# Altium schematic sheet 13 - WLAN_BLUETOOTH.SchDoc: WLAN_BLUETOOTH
size A3; Date: 21-DEC-2018; Author: CR; CompanyName: Octavo Systems LLC; Address2: Austin,TX; Address3: USA; DocumentNumber: DK2 RefDes; Revision: C-01; SheetNumber: 13; SheetTotal: 14
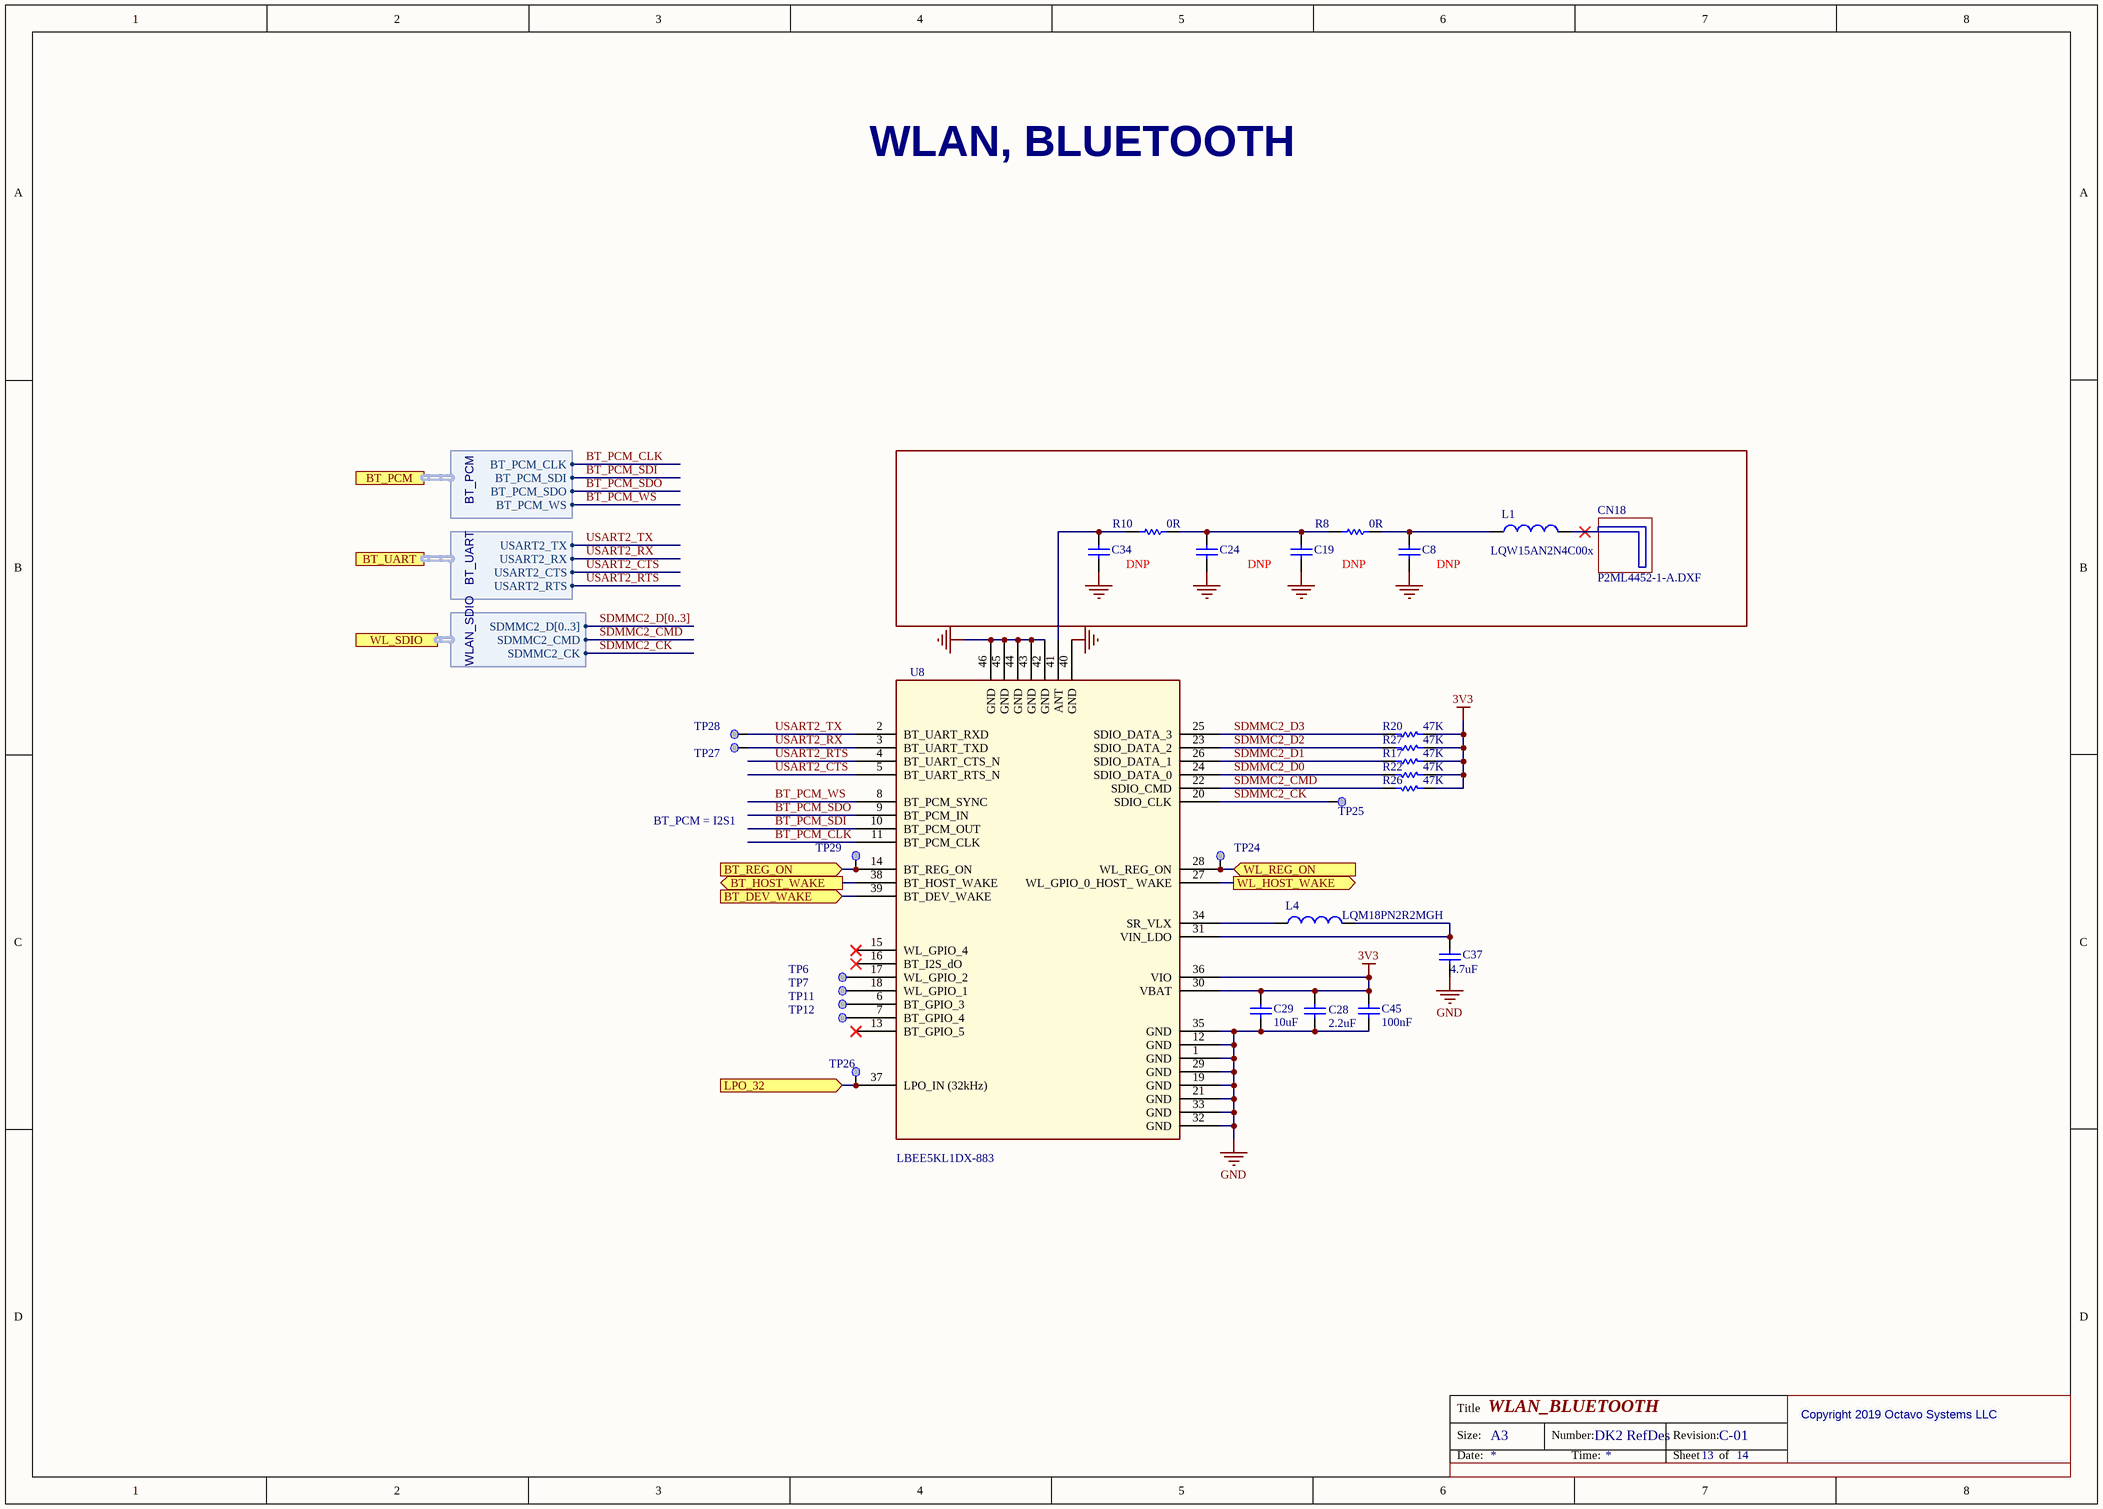
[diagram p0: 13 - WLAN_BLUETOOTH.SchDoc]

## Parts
C8  Capacitor  [C0402]  (value not drawn)  (no BOM)
C19  Capacitor  [C0402]  (value not drawn)  (no BOM)
C24  Capacitor  [C0402]  (value not drawn)  (no BOM)
C28  value 2.2uF  [C0603]  (hidden comment: Capacitor)
C29  value 10uF  [C0603]  (hidden comment: Capacitor)
C34  Capacitor  [C0402]  (value not drawn)  (no BOM)
C37  value 4.7uF  [C0402]
C45  value 100nF  [C0402]
CN18  value P2ML4452-1-A.DXF  [ANT_MURATA_TYPE-1-DX_P2ML4452-1-A_DXF]  (hidden comment: antenna_Wifi_BLE_Murata)  (graphical)
L1  value LQW15AN2N4C00x  [IND_0402_MURATA_LQW15AN2N4C00X]  (hidden comment: Inductor)
L4  value LQM18PN2R2MGH  [L0603]  (hidden comment: Inductor)
R8  value 0R  [R0402]  (hidden comment: Resistor)
R10  value 0R  [R0402]  (hidden comment: Resistor)
R17  value 47K  [R0402]  (hidden comment: Resistor)
R20  value 47K  [R0402]  (hidden comment: Resistor)
R22  value 47K  [R0402]  (hidden comment: Resistor)
R26  value 47K  [R0402]  (hidden comment: Resistor)
R27  value 47K  [R0402]  (hidden comment: Resistor)
TP6  Test Point  [TP_SMD_1MM]  (value not drawn)  (no BOM)
TP7  Test Point  [TP_SMD_1MM]  (value not drawn)  (no BOM)
TP11  Test Point  [TP_SMD_1MM]  (value not drawn)  (no BOM)
TP12  Test Point  [TP_SMD_1MM]  (value not drawn)  (no BOM)
TP24  Test Point  [TP_SMD_0-6MM]  (value not drawn)  (no BOM)
TP25  Test Point  [TP_SMD_0-6MM]  (value not drawn)  (no BOM)
TP26  Test Point  [TP_SMD_0-6MM]  (value not drawn)  (no BOM)
TP27  Test Point  [TP_SMD_0-6MM]  (value not drawn)  (no BOM)
TP28  Test Point  [TP_SMD_0-6MM]  (value not drawn)  (no BOM)
TP29  Test Point  [TP_SMD_0-6MM]  (value not drawn)  (no BOM)
U8  LBEE5KL1DX-883  [MOD_WLAN-BT_MURATA_LBEE5KL1DX-883]

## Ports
BT_DEV_WAKE (in), BT_HOST_WAKE (out), BT_PCM (harness BT_PCM), BT_REG_ON (in), BT_UART (harness BT_UART), LPO_32 (in), WL_HOST_WAKE (out), WL_REG_ON (in), WL_SDIO (harness WLAN_SDIO)

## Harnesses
BT_PCM: BT_PCM_CLK, BT_PCM_SDI, BT_PCM_SDO, BT_PCM_WS
BT_UART: USART2_TX, USART2_RX, USART2_CTS, USART2_RTS
WLAN_SDIO: SDMMC2_D[0..3], SDMMC2_CMD, SDMMC2_CK

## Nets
3V3: C28.2 C29.2 C45.2 R17.1 R20.1 R22.1 R26.1 R27.1 U8.30(VBAT) U8.36(VIO)
GND: C8.1 C19.1 C24.1 C28.1 C29.1 C34.1 C37.1 C45.1 U8.1(GND) U8.12(GND) U8.19(GND) U8.21(GND) U8.29(GND) U8.32(GND) U8.33(GND) U8.35(GND) U8.40(GND) U8.42(GND) U8.43(GND) U8.44(GND) U8.45(GND) U8.46(GND)
BT_DEV_WAKE: U8.39(BT_DEV_WAKE) ; port BT_DEV_WAKE
BT_HOST_WAKE: U8.38(BT_HOST_WAKE) ; port BT_HOST_WAKE
BT_PCM_CLK: U8.11(BT_PCM_CLK) ; port BT_PCM.BT_PCM_CLK
BT_PCM_SDI: U8.10(BT_PCM_OUT) ; port BT_PCM.BT_PCM_SDI
BT_PCM_SDO: U8.9(BT_PCM_IN) ; port BT_PCM.BT_PCM_SDO
BT_PCM_WS: U8.8(BT_PCM_SYNC) ; port BT_PCM.BT_PCM_WS
BT_REG_ON: TP29.1 U8.14(BT_REG_ON) ; port BT_REG_ON
LPO_32: TP26.1 U8.37(LPO_IN_(32kHz)) ; port LPO_32
SDMMC2_CK: TP25.1 U8.20(SDIO_CLK) ; port WL_SDIO.SDMMC2_CK
SDMMC2_CMD: R26.2 U8.22(SDIO_CMD) ; port WL_SDIO.SDMMC2_CMD
SDMMC2_D0: R22.2 U8.24(SDIO_DATA_0)
SDMMC2_D1: R17.2 U8.26(SDIO_DATA_1)
SDMMC2_D2: R27.2 U8.23(SDIO_DATA_2)
SDMMC2_D3: R20.2 U8.25(SDIO_DATA_3)
USART2_CTS: U8.5(BT_UART_RTS_N) ; port BT_UART.USART2_CTS
USART2_RTS: U8.4(BT_UART_CTS_N) ; port BT_UART.USART2_RTS
USART2_RX: TP27.1 U8.3(BT_UART_TXD) ; port BT_UART.USART2_RX
USART2_TX: TP28.1 U8.2(BT_UART_RXD) ; port BT_UART.USART2_TX
WL_HOST_WAKE: U8.27(WL_GPIO_0_HOST__WAKE) ; port WL_HOST_WAKE
WL_REG_ON: TP24.1 U8.28(WL_REG_ON) ; port WL_REG_ON
NetC8_2: C8.2 L1.1 R8.1
NetC19_2: C19.2 C24.2 R8.2 R10.1
NetC34_2: C34.2 R10.2 U8.41(ANT)
NetC37_2: C37.2 L4.2 U8.31(VIN_LDO)
NetL4_1: L4.1 U8.34(SR_VLX)
NetTP6_1: TP6.1 U8.17(WL_GPIO_2)
NetTP7_1: TP7.1 U8.18(WL_GPIO_1)
NetTP11_1: TP11.1 U8.6(BT_GPIO_3)
NetTP12_1: TP12.1 U8.7(BT_GPIO_4)

Not connected (* = marked no-connect by the designer): L1 2*; U8 13(BT_GPIO_5)* 15(WL_GPIO_4)* 16(BT_I2S_dO)*

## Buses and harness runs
bus SDMMC2_D[0..3]

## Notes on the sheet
- WLAN, BLUETOOTH
- DNP
- (near C8) DNP
- BT_PCM = I2S1
- Copyright 2019 Octavo Systems LLC

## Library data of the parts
C8 C19 C24 C34 = MCD-00200: Capacitor, MLCC, 12pF, 50V, NPO, 5%, 0402, T=0,5mm; Manufacturer_Part_Number: CC0402JRNPO9BN120; Manufacturer: YAGEO; Provided_By: Subcon
C28 = MCD-00012: Capacitor, MLCC, 2.2uF, 10V, X5R, 10%, 0603, T=0,8mm; Manufacturer_Part_Number: CC0603KRX5R6BB225; Manufacturer: YAGEO; Alternate_Manufacturer_Part_Number: C0603C225K8PACTU; Alternate_Manufacturer: KEMET; Provided_By: Subcon; Initial_Board_Reference: MB1274
C29 = MCD-00099: Capacitor, MLCC, 10uF, 10V, X5R, 10%, 0603, T=0,8mm; Manufacturer_Part_Number: GRM188R61A106KE69D; Manufacturer: MURATA; ECCN_US: EAR99; ECCN_EU: NEC; Provided_By: Subcon; Initial_Board_Reference: MB1262
C37 = MCD-01356: Capacitor, MLCC, 4.7uF, 6V3, X5R, 20%, 0402, T=0,5mm; Manufacturer_Part_Number: GRM155R60J475ME47; Manufacturer: MURATA; Provided_By: SUBCO; Initial_Board_Reference: MB1372; Item Type: Item; Path: ws/MCD_ApplicationBoards/Lists/MCDPARTSdatabase
C45 = MCD-00006: Capacitor,100nF,16V,X7R,10%,0402; Manufacturer_Part_Number: CC0402KRX7R7BB104; Manufacturer: YAGEO; Provided_By: Subcon; Initial_Board_Reference: MB1274
CN18 = MCD-00656: Murata_Type1DX_AntennaDesign_P2ML4452-1-A.DXF; Part_Type: Misc; Manufacturer: MURATA; Initial_Board_Reference: MB1272
L1 = MCD-00657: Inductor,2.4nH,+-0.2nH,0.05R,0.85A,0402; Manufacturer: MURATA; Provided_By: Subcon; Initial_Board_Reference: MB1272
L4 = MCD-00659: Inductor, 2.2µH, 20%, Isat 0.35A, DCR 0.2Ohm, 0603; Manufacturer: MURATA; Provided_By: Subcon; Initial_Board_Reference: MB1272
R8 R10 = MCD-00052: Resistor,0R,0402,5%,1/16W; Manufacturer_Part_Number: RC0402JR-070RL; Manufacturer: YAGEO; Provided_By: Subcon; Initial_Board_Reference: MB1274
R17 R20 R22 R26 R27 = MCD-00063: Resistor,47K,0402,1%,1/16W; Manufacturer_Part_Number: RC0402FR-0747KL; Manufacturer: YAGEO; Provided_By: Subcon; Initial_Board_Reference: MB1274
TP6 TP7 TP11 TP12 = MCD-00074: Test Point 1mm; Part_Type: Mechanical; Initial_Board_Reference: MB1274
TP24-TP29 = MCD-00631: Test Point 0.6mm; Part_Type: Mechanical; Initial_Board_Reference: MB1264
U8 = MCD-00268: IEEE802.11b/g/n W-LAN + Bluetooth 4.1+EDR module; Manufacturer: MURATA; Part_Type: IC; Provided_By: Subcon; ECCN_US: 5A992C; Initial_Board_Reference: MB1272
